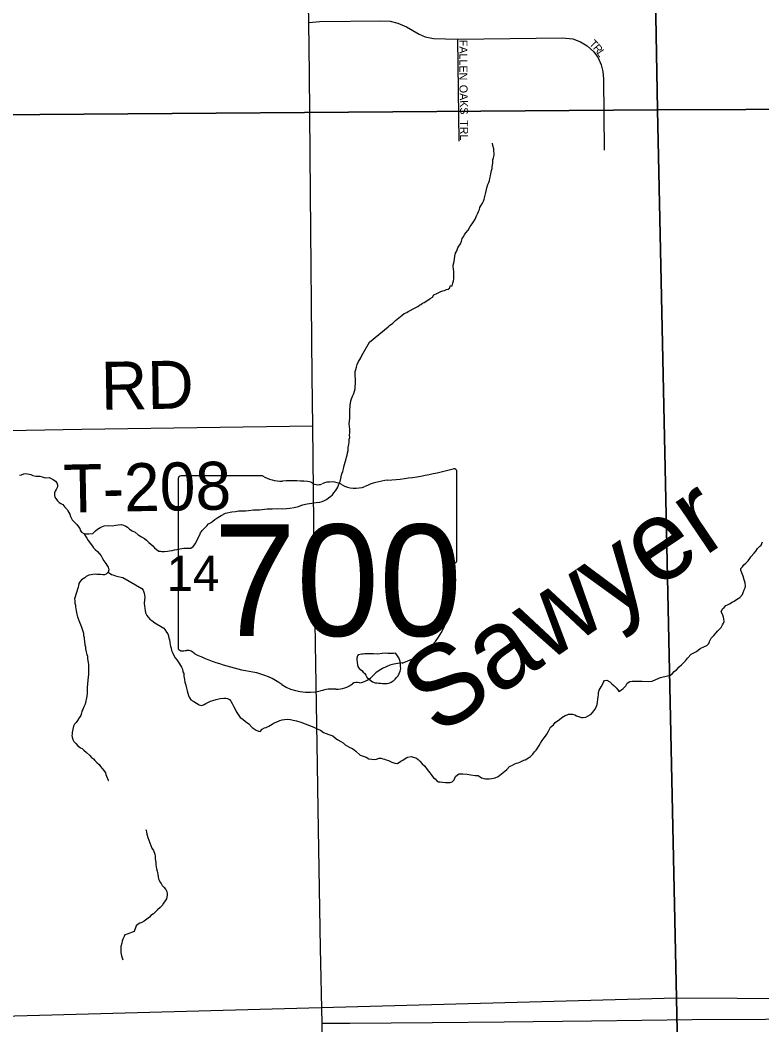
# Model space of a CAD drawing. Extents: x 10.6 to 44.6, y -2.6 to 23.4.
# Drawn here: x 17.431 to 18.308, y 16.595 to 17.784 of the extents above; entities that cross this region are included whole.
import ezdxf

# ---------------------------------------------------------------- set-up
doc = ezdxf.new("R2010")
doc.units = 0
for name, color, linetype in [('GM_X_Minor_Lake', 7, 'Continuous'), ('GM_X_Minor_River', 7, 'Continuous'), ('GM_X_Minor_River_Text', 7, 'Continuous'), ('GM_X_Section', 7, 'Continuous'), ('GM_X_Section_Text', 7, 'Continuous'), ('GM_X_State_Route', 7, 'Continuous'), ('GM_X_State_Shield', 7, 'Continuous'), ('GM_X_Township_Road', 7, 'Continuous'), ('GM_X_Township_Road_Text', 7, 'Continuous'), ('GM_X_Township_Subdivision', 7, 'Continuous'), ('GM_X_Township_Subdivision_Text', 7, 'Continuous')]:
    doc.layers.add(name, color=color, linetype=linetype)

msp = doc.modelspace()

# ---------------------------------------------------------------- linework, layer by layer
at = {"layer": 'GM_X_Minor_Lake'}
for points in [[(17.835, 17.0335), (17.8308, 17.0327), (17.8305, 17.0315), (17.8301, 17.0315), (17.829, 17.0288), (17.8291, 17.0269), (17.8295, 17.0235), (17.83, 17.0208), (17.8304, 17.019), (17.832, 17.0167), (17.8351, 17.0141), (17.8366, 17.0122), (17.8386, 17.0108), (17.8398, 17.0085), (17.841, 17.0063), (17.8441, 17.0037), (17.8479, 17.0007), (17.851, 16.9996), (17.8529, 16.9997), (17.8548, 16.9993), (17.8571, 16.999), (17.8594, 16.9987), (17.8617, 16.9987), (17.8651, 16.9988), (17.8681, 16.9996), (17.87, 17.0004), (17.8722, 17.0018)], [(17.8722, 17.0018), (17.8726, 17.002), (17.8745, 17.004), (17.876, 17.0059), (17.8782, 17.0079), (17.8793, 17.0105), (17.8804, 17.0132), (17.8811, 17.0167), (17.881, 17.019), (17.8809, 17.022), (17.8805, 17.025), (17.8797, 17.0273), (17.8789, 17.0292), (17.8765, 17.0326), (17.8749, 17.0348), (17.8727, 17.0344), (17.8677, 17.0343), (17.8658, 17.0342), (17.8631, 17.0345), (17.8593, 17.0341), (17.854, 17.0336), (17.8491, 17.0338), (17.843, 17.0337), (17.8388, 17.034), (17.8365, 17.0335), (17.835, 17.0335)]]:
    msp.add_lwpolyline(points, dxfattribs=at)
at = {"layer": 'GM_X_Minor_River'}
for points in [[(17.8442, 17.4026), (17.8661, 17.4207), (17.868, 17.4222), (17.8717, 17.4253), (17.8751, 17.4285), (17.8769, 17.43), (17.8788, 17.4316), (17.8807, 17.4331), (17.8829, 17.4347), (17.8852, 17.4367), (17.8882, 17.4379), (17.8901, 17.439), (17.8923, 17.4402), (17.8957, 17.4422), (17.8976, 17.443), (17.9013, 17.445), (17.9032, 17.4466), (17.9051, 17.4474), (17.907, 17.4489), (17.9088, 17.4497), (17.9122, 17.4517), (17.916, 17.4544), (17.9186, 17.456), (17.9204, 17.4587), (17.9238, 17.4603), (17.9284, 17.4627), (17.931, 17.4635), (17.9329, 17.4639), (17.9351, 17.4651), (17.9374, 17.4655), (17.9393, 17.4671), (17.9396, 17.4694), (17.9419, 17.4694), (17.9426, 17.4725), (17.9437, 17.4752), (17.944, 17.4778), (17.944, 17.4805), (17.9439, 17.4832), (17.9438, 17.4862), (17.9434, 17.4896), (17.9433, 17.4919), (17.9433, 17.4938), (17.9443, 17.498), (17.9447, 17.5007), (17.9453, 17.5045), (17.946, 17.5079), (17.9471, 17.5098), (17.9478, 17.5121), (17.9489, 17.5144), (17.95, 17.5164), (17.9519, 17.5191), (17.953, 17.5221), (17.954, 17.5252), (17.9551, 17.5271), (17.9566, 17.5298), (17.9581, 17.5321), (17.961, 17.5352), (17.9632, 17.5394), (17.9655, 17.5425), (17.9673, 17.5452), (17.9691, 17.5483), (17.9706, 17.5521), (17.9724, 17.5552), (17.9731, 17.5571), (17.9742, 17.5598), (17.9749, 17.5621), (17.976, 17.564), (17.9779, 17.5671), (17.979, 17.5694), (17.9797, 17.5717), (17.9818, 17.5797), (17.9825, 17.5832), (17.9832, 17.5851), (17.9842, 17.5893), (17.9853, 17.5916), (17.986, 17.5939), (17.9864, 17.5962), (17.9874, 17.5996), (17.9878, 17.6019), (17.9881, 17.6038), (17.9885, 17.6057), (17.9892, 17.608), (17.9895, 17.6099), (17.9898, 17.6126), (17.9902, 17.6145), (17.9901, 17.6183), (17.9908, 17.6206), (17.9915, 17.624), (17.9915, 17.6259), (17.9914, 17.629), (17.9913, 17.6313), (17.9901, 17.6354), (17.9897, 17.6381)], [(17.7648, 17.21), (17.7704, 17.2113), (17.7761, 17.2122), (17.7811, 17.213), (17.7856, 17.2135), (17.7883, 17.2143), (17.7909, 17.2155), (17.7935, 17.2167), (17.7958, 17.2183), (17.7984, 17.2203), (17.8006, 17.2222), (17.8021, 17.2242), (17.804, 17.2269), (17.8054, 17.2292), (17.8069, 17.2311), (17.808, 17.2346), (17.8094, 17.2377), (17.8115, 17.2468), (17.8126, 17.2495), (17.8133, 17.2526), (17.814, 17.2553), (17.8147, 17.2579), (17.8154, 17.2606), (17.8161, 17.2629), (17.8168, 17.2664), (17.8178, 17.269), (17.8182, 17.2717), (17.8189, 17.2744), (17.8191, 17.2782), (17.8198, 17.2816), (17.8201, 17.2847), (17.8201, 17.2877), (17.8208, 17.29), (17.8207, 17.2927), (17.821, 17.2958), (17.8209, 17.2996), (17.82, 17.306), (17.821, 17.3129), (17.8208, 17.3205), (17.8214, 17.3281), (17.8221, 17.3331), (17.8228, 17.3358), (17.8246, 17.3396), (17.8257, 17.3419), (17.8264, 17.3446), (17.8271, 17.3473), (17.8274, 17.3507), (17.8277, 17.3534), (17.8276, 17.3564), (17.8276, 17.3595), (17.8271, 17.3625), (17.8271, 17.3651), (17.8274, 17.3678), (17.8281, 17.3705), (17.8288, 17.3732), (17.8295, 17.3762), (17.8313, 17.3797), (17.8328, 17.382), (17.8338, 17.3843), (17.8353, 17.387), (17.8442, 17.4026)], [(17.4299, 17.2454), (17.4325, 17.2458), (17.4352, 17.2467), (17.4371, 17.2471), (17.4394, 17.2468), (17.4413, 17.2464), (17.4436, 17.2461), (17.4459, 17.245), (17.4493, 17.2443), (17.4512, 17.244), (17.4543, 17.2441), (17.4569, 17.2434), (17.4592, 17.2426), (17.4611, 17.2423), (17.465, 17.2424), (17.4676, 17.2413), (17.47, 17.2402), (17.4727, 17.238), (17.4742, 17.2361)], [(17.4742, 17.2361), (17.475, 17.2339), (17.4751, 17.2316), (17.4733, 17.2285), (17.4722, 17.2262), (17.4715, 17.2243), (17.4715, 17.2212), (17.4719, 17.2193), (17.4731, 17.2175), (17.4751, 17.2148), (17.477, 17.213), (17.479, 17.2119), (17.4813, 17.2104), (17.4836, 17.2074), (17.4864, 17.2048), (17.4872, 17.2029), (17.4883, 17.2011), (17.4895, 17.1992), (17.4904, 17.1965), (17.4924, 17.1924), (17.4955, 17.1894), (17.4978, 17.1868), (17.4998, 17.1842), (17.5013, 17.182), (17.5018, 17.1801), (17.5033, 17.1778), (17.506, 17.1764), (17.5091, 17.176), (17.5121, 17.1757), (17.5167, 17.1762), (17.52, 17.1793), (17.5223, 17.1813), (17.5245, 17.1825), (17.5264, 17.1837), (17.5302, 17.1853), (17.5355, 17.1858), (17.5397, 17.1855), (17.5439, 17.186), (17.5469, 17.1864), (17.5503, 17.1869), (17.553, 17.1862), (17.5557, 17.1851), (17.558, 17.1836), (17.5603, 17.1814), (17.5634, 17.1796), (17.5669, 17.1777), (17.5704, 17.1748), (17.5746, 17.1722), (17.5781, 17.1704), (17.5804, 17.1682), (17.5831, 17.1655), (17.5855, 17.1637), (17.5878, 17.1615), (17.5898, 17.1592), (17.5921, 17.1574), (17.5948, 17.1555), (17.5967, 17.1552), (17.5986, 17.1549), (17.6016, 17.1549), (17.6051, 17.1554), (17.6077, 17.1558), (17.6108, 17.1563), (17.6134, 17.1571), (17.6164, 17.1572), (17.6198, 17.158), (17.6244, 17.1589), (17.6286, 17.159), (17.6328, 17.1591), (17.6354, 17.161), (17.6383, 17.1645), (17.6416, 17.1711), (17.6434, 17.1745), (17.6441, 17.1772), (17.6467, 17.1803), (17.649, 17.1826), (17.6516, 17.1854), (17.6538, 17.1877), (17.6568, 17.1893), (17.659, 17.1909), (17.6613, 17.1928), (17.6647, 17.1952), (17.6688, 17.1976), (17.6737, 17.2003), (17.6812, 17.202), (17.6858, 17.2025), (17.6896, 17.203), (17.6926, 17.203), (17.6949, 17.2031), (17.6976, 17.2032), (17.701, 17.2036), (17.7071, 17.2041), (17.7139, 17.2043), (17.723, 17.2053), (17.7291, 17.2054), (17.7359, 17.2059), (17.7413, 17.2053), (17.7458, 17.2058), (17.75, 17.2062), (17.7549, 17.2071), (17.7602, 17.2084), (17.7648, 17.21)], [(17.506, 17.1764), (17.5096, 17.1707), (17.5112, 17.1681), (17.5163, 17.1614), (17.5175, 17.1595), (17.5194, 17.1573), (17.5225, 17.155), (17.5248, 17.1524), (17.5268, 17.1498), (17.5284, 17.1468), (17.53, 17.1438), (17.5323, 17.1408), (17.5335, 17.1389), (17.5351, 17.1363), (17.5356, 17.1333), (17.5349, 17.1306), (17.5326, 17.1283), (17.5307, 17.1275), (17.5285, 17.1274), (17.5258, 17.1277), (17.5235, 17.1277), (17.5216, 17.1276), (17.5197, 17.128), (17.5167, 17.1279), (17.5148, 17.1275), (17.5121, 17.127), (17.5091, 17.1254), (17.5072, 17.1239), (17.5054, 17.1227), (17.5035, 17.1215), (17.5013, 17.1192), (17.5002, 17.1172), (17.4998, 17.1142), (17.4994, 17.1126)], [(18.2849, 17.1297), (18.2836, 17.1327), (18.2836, 17.135), (18.2854, 17.137), (18.2873, 17.1393), (18.2895, 17.1412), (18.2921, 17.144), (18.2944, 17.1467), (18.2955, 17.1486), (18.2995, 17.1529), (18.3014, 17.1552), (18.3032, 17.1587), (18.3058, 17.161), (18.3077, 17.1626), (18.3091, 17.1664)], [(17.5349, 17.1306), (17.5391, 17.1276), (17.5418, 17.1269), (17.5437, 17.1262), (17.5468, 17.1255), (17.5502, 17.1248), (17.5525, 17.1244)], [(17.5525, 17.1244), (17.5749, 17.1113), (17.5764, 17.1091), (17.5777, 17.1057), (17.5781, 17.1038), (17.5782, 17.1007), (17.5778, 17.0977), (17.5776, 17.0935), (17.578, 17.0905), (17.5785, 17.0874), (17.5789, 17.0852), (17.5793, 17.0825), (17.5809, 17.0791), (17.5821, 17.0772), (17.5841, 17.075), (17.5868, 17.0732), (17.5903, 17.0706), (17.5987, 17.0654), (17.6007, 17.0643), (17.6022, 17.0625), (17.6038, 17.0595), (17.6054, 17.0576), (17.6062, 17.055), (17.6067, 17.0523), (17.6075, 17.0504), (17.6079, 17.0478), (17.6084, 17.0447), (17.6088, 17.0428), (17.6096, 17.0406), (17.61, 17.0379), (17.6109, 17.0353), (17.6125, 17.0319), (17.6144, 17.0293), (17.6164, 17.0267), (17.6195, 17.0222), (17.6219, 17.018), (17.6231, 17.0158), (17.6235, 17.0127), (17.6244, 17.0105), (17.6244, 17.0074), (17.6253, 17.0036), (17.6257, 17.0002), (17.627, 16.9968), (17.6278, 16.9934), (17.6286, 16.99), (17.6291, 16.9874), (17.6299, 16.9847), (17.6307, 16.9828), (17.6327, 16.9795), (17.6365, 16.9773), (17.6396, 16.9754), (17.6427, 16.9736), (17.6458, 16.9729), (17.6484, 16.9741), (17.6507, 16.9753), (17.6529, 16.9765), (17.6559, 16.9777), (17.659, 16.9785), (17.6627, 16.9798), (17.6673, 16.981), (17.6718, 16.9815), (17.6741, 16.9815), (17.676, 16.9812), (17.6787, 16.9797), (17.6803, 16.9779), (17.6815, 16.9752), (17.6831, 16.9718), (17.685, 16.9692), (17.6862, 16.9666), (17.6871, 16.9643), (17.6886, 16.9621), (17.691, 16.9587), (17.6945, 16.9565), (17.6976, 16.9539), (17.7014, 16.951), (17.7053, 16.9469), (17.71, 16.9435), (17.713, 16.9425), (17.715, 16.9421), (17.7172, 16.9448), (17.7198, 16.9464), (17.7221, 16.9469), (17.7251, 16.9484), (17.727, 16.9493), (17.7292, 16.9508), (17.7315, 16.9524), (17.7337, 16.9532), (17.7379, 16.9552), (17.7409, 16.9557), (17.7436, 16.9561)], [(18.0618, 16.95), (18.064, 16.9527), (18.0666, 16.9547), (18.0685, 16.9559), (18.0719, 16.9586), (18.0737, 16.9598), (18.0756, 16.961), (18.0779, 16.9618), (18.0798, 16.9626), (18.0824, 16.9626), (18.0843, 16.9627), (18.087, 16.9616), (18.0893, 16.9605), (18.0913, 16.9598), (18.0951, 16.9587), (18.097, 16.9584), (18.1, 16.9589), (18.1064, 16.9624), (18.1086, 16.9648), (18.1108, 16.9682), (18.113, 16.9725), (18.1141, 16.9763), (18.1144, 16.9801), (18.1147, 16.9832), (18.115, 16.9855), (18.115, 16.9881), (18.116, 16.9908), (18.1182, 16.995), (18.1197, 16.9977), (18.1211, 17.0004), (18.1222, 17.0024), (18.1249, 17.0028), (18.1287, 17.0006), (18.1311, 16.9984), (18.1338, 16.9962), (18.1361, 16.9935), (18.1381, 16.9913), (18.1393, 16.9894), (18.1423, 16.9914), (18.1445, 16.993), (18.1475, 16.9961), (18.1489, 16.9992), (18.1523, 17.0011), (18.155, 17.0016), (18.1573, 17.0016), (18.1592, 17.0017), (18.1618, 17.0014), (18.1645, 17.0014), (18.1668, 17.0015), (18.1744, 17.0013), (18.1786, 17.0014), (18.1831, 17.0037), (18.1884, 17.0058), (18.1967, 17.0079), (18.2005, 17.0087), (18.2023, 17.0103), (18.2046, 17.013), (18.2079, 17.0153), (18.2105, 17.0184), (18.2135, 17.0208), (18.2158, 17.0231), (18.218, 17.0255), (18.2206, 17.0286), (18.2246, 17.0336), (18.231, 17.0368), (18.2355, 17.0403), (18.2404, 17.0427), (18.2434, 17.0439), (18.2457, 17.0463), (18.2464, 17.0486), (18.2486, 17.0524), (18.2515, 17.0555), (18.2541, 17.0582), (18.2564, 17.061), (18.2601, 17.0652), (18.2619, 17.0683), (18.263, 17.0702), (18.2637, 17.0722), (18.2636, 17.0752), (18.2632, 17.0771), (18.262, 17.0809), (18.2604, 17.0835), (18.2619, 17.087), (18.2637, 17.0889), (18.266, 17.0909), (18.2678, 17.0917), (18.2701, 17.0932), (18.2735, 17.0952), (18.2757, 17.0964), (18.2783, 17.098), (18.2806, 17.0992), (18.2825, 17.1007), (18.2854, 17.1042), (18.2865, 17.1065), (18.2876, 17.1096), (18.2887, 17.1119), (18.289, 17.1138), (18.2885, 17.118), (18.2877, 17.1214), (18.2865, 17.1256), (18.2849, 17.1297)], [(17.4994, 17.1126), (17.4952, 17.0989), (17.4957, 17.0966), (17.4957, 17.0939), (17.4962, 17.0913), (17.4962, 17.0894), (17.4967, 17.0871), (17.4971, 17.0848), (17.4979, 17.081), (17.4988, 17.0776), (17.5, 17.0746), (17.5012, 17.0712), (17.5024, 17.0686), (17.5036, 17.0656), (17.5057, 17.0584), (17.5057, 17.0557), (17.5066, 17.0531), (17.5066, 17.0508), (17.507, 17.0489), (17.5075, 17.0444), (17.508, 17.0421), (17.508, 17.0398), (17.5089, 17.0364), (17.5097, 17.033), (17.5105, 17.0311), (17.5106, 17.0284), (17.511, 17.0258), (17.5114, 17.0235), (17.5115, 17.0212), (17.5116, 17.0178), (17.5117, 17.0136), (17.5117, 17.0098), (17.5114, 17.0064), (17.5111, 17.0026), (17.5105, 16.9984), (17.5102, 16.9942), (17.5103, 16.9911), (17.51, 16.9873), (17.5097, 16.9839), (17.5076, 16.9743), (17.5062, 16.9713), (17.5051, 16.9682), (17.504, 16.9659), (17.5033, 16.9636), (17.5026, 16.9609), (17.5007, 16.9582), (17.4985, 16.9551), (17.4971, 16.9528), (17.4952, 16.9505), (17.4941, 16.9485), (17.4931, 16.9447), (17.4927, 16.9428), (17.4924, 16.9409), (17.4924, 16.939), (17.4921, 16.9371), (17.4925, 16.9352), (17.4933, 16.9325), (17.4945, 16.9303), (17.4969, 16.9277), (17.4992, 16.9251), (17.5023, 16.9228), (17.5042, 16.9218), (17.5062, 16.9199), (17.5093, 16.9173), (17.5128, 16.914), (17.5151, 16.9113), (17.5175, 16.9095), (17.519, 16.9076), (17.5217, 16.9054), (17.5245, 16.9028), (17.526, 16.9006), (17.528, 16.8983), (17.53, 16.8957), (17.5319, 16.8931), (17.5323, 16.8912), (17.5331, 16.8893), (17.5348, 16.8844), (17.5348, 16.884), (17.5352, 16.884)], [(17.7436, 16.9561), (17.7474, 16.9566), (17.7508, 16.9563), (17.7538, 16.9556), (17.758, 16.9545), (17.763, 16.9531), (17.7784, 16.947), (17.7822, 16.9452), (17.7861, 16.9434), (17.7899, 16.9408), (17.7961, 16.9386), (17.8007, 16.9368), (17.8038, 16.9343), (17.8069, 16.932), (17.8104, 16.9302), (17.8131, 16.9284), (17.8154, 16.9261), (17.8181, 16.9247), (17.8208, 16.9232), (17.8242, 16.9218), (17.8281, 16.9188), (17.8332, 16.914), (17.8401, 16.9115), (17.8435, 16.9097), (17.847, 16.9094), (17.85, 16.909), (17.8523, 16.9091), (17.8557, 16.9103), (17.858, 16.9104), (17.8599, 16.9096), (17.8618, 16.9093), (17.8641, 16.9086), (17.8668, 16.9075), (17.8707, 16.9057), (17.8741, 16.9046), (17.8772, 16.9043), (17.8813, 16.9067), (17.8835, 16.9079), (17.8854, 16.9091), (17.8892, 16.9115), (17.8933, 16.9123), (17.8998, 16.9106), (17.9018, 16.9087), (17.9037, 16.9068), (17.9065, 16.9039), (17.9096, 16.9009), (17.9123, 16.8971), (17.9155, 16.893), (17.9178, 16.89), (17.9198, 16.887), (17.9217, 16.8859), (17.9237, 16.8837), (17.926, 16.8826), (17.9279, 16.8823), (17.9306, 16.882), (17.934, 16.8816), (17.9374, 16.8817), (17.9397, 16.8818), (17.942, 16.8826), (17.9442, 16.8849), (17.946, 16.8888), (17.9482, 16.8907), (17.9501, 16.8919), (17.9547, 16.892), (17.9596, 16.8914), (17.9642, 16.8907), (17.9692, 16.8901), (17.9726, 16.8898), (17.9769, 16.8872), (17.9795, 16.8865), (17.9814, 16.8861), (17.9856, 16.8859), (17.9891, 16.8863), (17.9928, 16.8872), (17.9966, 16.8888), (18.0045, 16.895), (18.0067, 16.897), (18.01, 16.9005), (18.0134, 16.9021), (18.0161, 16.9037), (18.0183, 16.9045), (18.0202, 16.9049), (18.0221, 16.9057), (18.0243, 16.9069), (18.0266, 16.9081), (18.0285, 16.9085), (18.0322, 16.9109), (18.0345, 16.9125), (18.0375, 16.9152), (18.0393, 16.9179), (18.0412, 16.9198), (18.043, 16.9222), (18.0449, 16.9253), (18.0467, 16.9283), (18.0485, 16.9314), (18.0507, 16.9345), (18.0526, 16.9365), (18.0541, 16.9388), (18.0559, 16.9423), (18.0584, 16.9473), (18.0618, 16.95)], [(17.5795, 16.826), (17.5799, 16.8249), (17.5803, 16.8234), (17.5808, 16.8204), (17.582, 16.8166), (17.5868, 16.8041), (17.5888, 16.8011), (17.59, 16.797), (17.5905, 16.7943), (17.5906, 16.7913), (17.591, 16.7894), (17.5914, 16.7867), (17.5915, 16.7841), (17.5919, 16.7818), (17.5923, 16.7795), (17.5928, 16.7769), (17.5932, 16.775), (17.5936, 16.7727), (17.5941, 16.7701), (17.5945, 16.7678), (17.5953, 16.7659), (17.5961, 16.764), (17.5977, 16.7621), (17.5989, 16.7599), (17.6008, 16.7577), (17.6032, 16.755), (17.6044, 16.7528), (17.6048, 16.7505), (17.6048, 16.7486), (17.6045, 16.7459), (17.6038, 16.744), (17.6023, 16.7417), (17.6005, 16.739), (17.5987, 16.7363), (17.5964, 16.7336), (17.5935, 16.7309), (17.5908, 16.7285), (17.5886, 16.7262), (17.5856, 16.7242), (17.5838, 16.7223), (17.5808, 16.7199), (17.5774, 16.7175), (17.5748, 16.716), (17.5725, 16.7152), (17.5706, 16.714), (17.568, 16.712), (17.5659, 16.7055), (17.5576, 16.7023), (17.5546, 16.7014), (17.5538, 16.6995), (17.5524, 16.6964), (17.5517, 16.6938), (17.551, 16.6915), (17.5499, 16.6876), (17.55, 16.6842), (17.55, 16.6823), (17.5501, 16.6804), (17.5509, 16.6766), (17.5514, 16.674), (17.5522, 16.6717)]]:
    msp.add_lwpolyline(points, dxfattribs=at)
at = {"layer": 'GM_X_Section'}
for points in [[(17.2198, 18.8008), (18.1646, 18.8031), (18.1656, 18.7612), (18.1848, 17.6775), (17.2448, 17.6704)], [(18.1656, 18.7612), (19.1006, 18.7791), (19.125, 17.681), (18.1848, 17.6775)], [(18.1848, 17.6775), (19.125, 17.681), (19.1418, 16.6213), (18.2074, 16.6265)], [(17.2448, 17.6704), (18.1848, 17.6775), (18.2074, 16.6265), (17.2647, 16.6007)]]:
    msp.add_lwpolyline(points, close=True, dxfattribs=at)
for points in [[(18.2299, 15.5267), (18.2074, 16.6265), (17.2647, 16.6007), (17.2881, 15.5267)], [(19.1603, 15.5267), (19.1419, 16.6116), (19.1419, 16.6144), (19.1418, 16.6213), (18.2074, 16.6265), (18.2299, 15.5267)]]:
    msp.add_lwpolyline(points, dxfattribs=at)
at = {"layer": 'GM_X_State_Route'}
msp.add_lwpolyline([(17.8012, 15.5267), (17.7999, 15.6245), (17.7994, 15.6969), (17.798, 15.8329), (17.7956, 16.0407), (17.7937, 16.2499), (17.7904, 16.4688), (17.788, 16.5964), (17.7861, 16.6856), (17.7836, 16.85), (17.7826, 16.9026), (17.7801, 17.0459), (17.7792, 17.124), (17.7789, 17.1502), (17.7773, 17.3034), (17.7765, 17.3624), (17.7744, 17.5784), (17.7731, 17.7202), (17.7723, 17.7811), (17.7695, 17.9272), (17.7683, 17.9968), (17.7654, 18.1426), (17.7636, 18.2173)], dxfattribs=at)
at = {"layer": 'GM_X_State_Shield'}
for p, q in [((17.6179, 17.2412), (17.6179, 17.041)), ((17.7177, 17.2446), (17.6212, 17.2446)), ((17.9475, 17.1449), (17.9475, 17.2496)), ((17.9475, 17.1449), (17.9475, 17.1449))]:
    msp.add_line(p, q, dxfattribs=at)
for centre, major_axis, start_param, end_param in [((17.8301, 17.5174), (0.3495, 0), 4.814394, 5.042369), ((17.9439, 17.25), (0.00367, 0), 6.141152, 7.989035), ((17.6217, 17.2416), (0.00382, 0), 1.712693, 3.28349), ((17.7407, 17.2678), (0.037, 0), 4.042523, 4.731795), ((17.753, 17.1322), (0.133, 0), 1.404758, 1.657858), ((17.7831, 17.2426), (0.0107, 0), 3.836095, 5.185415), ((17.7988, 17.2195), (0.0222, 0), 0.950623, 2.079405), ((17.8275, 17.2512), (0.0267, 0), 4.081561, 5.145723), ((17.8747, 17.1835), (0.0703, 0), 1.699011, 2.107814), ((17.9436, 17.1445), (0.00393, 0), 5.05454, 6.418171), ((17.9467, 17.1372), (0.00568, 0), 1.883978, 3.671073), ((17.9105, 17.124), (0.0341, 0), 5.934695, 6.695948), ((17.9607, 17.1011), (0.0248, 0), 2.387724, 3.262537), ((17.8497, 17.0877), (0.0874, 0), 5.101752, 6.440018), ((17.6217, 17.0406), (0.00385, 0), 3.00124, 4.508301), ((17.6223, 17.0611), (0.0294, 0), 4.665946, 4.897461), ((17.6283, 17.0295), (0.0106, 0), 0.519207, 1.627899), ((17.7622, 17.2093), (0.2524, 0), 4.195997, 4.488961), ((17.8866, 16.9849), (0.0479, 0), 1.647645, 2.488434), ((17.6869, 16.9511), (0.079, 0), 0.823519, 1.323587), ((17.8259, 17.0216), (0.0282, 0), 4.937069, 5.64225), ((17.7723, 17.0285), (0.0501, 0), 4.026481, 4.996735), ((17.8013, 16.9593), (0.0412, 0), 1.495662, 1.94098), ((17.8049, 17.0135), (0.0267, 0), 4.691044, 5.507374), ((17.8291, 16.9941), (0.00752, 0), 1.147584, 2.315152)]:
    msp.add_ellipse(centre, major_axis=major_axis, ratio=0.8, start_param=start_param, end_param=end_param, dxfattribs=at)
at = {"layer": 'GM_X_Township_Road'}
for points in [[(17.7773, 17.3034), (17.64, 17.3013), (17.5039, 17.2992), (17.3496, 17.2964), (17.2745, 17.2952), (17.2723, 17.2948)], [(19.5991, 16.6126), (19.5366, 16.6119), (19.2619, 16.6095), (18.9861, 16.6077), (18.7284, 16.6054), (18.6038, 16.6042), (18.5905, 16.6049), (18.4954, 16.6035), (18.4056, 16.6021), (18.3128, 16.6014), (18.2258, 16.6007), (18.107, 16.5993), (18.0035, 16.5982), (17.9186, 16.5972), (17.821, 16.5964), (17.788, 16.5964)]]:
    msp.add_lwpolyline(points, dxfattribs=at)
at = {"layer": 'GM_X_Township_Subdivision'}
for points in [[(17.7723, 17.7811), (17.7855, 17.7819), (17.8575, 17.783), (17.8686, 17.7824), (17.8779, 17.7803), (17.888, 17.7756), (17.9028, 17.7671), (17.9102, 17.7639), (17.92, 17.7621), (17.9483, 17.7613), (18.0724, 17.7626), (18.0846, 17.7615), (18.0939, 17.7581), (18.1018, 17.7531), (18.1095, 17.7462), (18.1148, 17.739), (18.1182, 17.7308), (18.1201, 17.7231), (18.1209, 17.7144), (18.1219, 17.6297)], [(17.9483, 17.7613), (17.9499, 17.6403)]]:
    msp.add_lwpolyline(points, dxfattribs=at)

# ---------------------------------------------------------------- texts
at = {"layer": 'GM_X_Minor_River_Text'}
msp.add_text('Sawyer', height=0.09476, rotation=34.0166, dxfattribs=at).set_placement((17.9248, 16.9356))
at = {"layer": 'GM_X_Section_Text'}
msp.add_text('14', height=0.04186, rotation=0, dxfattribs=at).set_placement((17.6042, 17.1083))
at = {"layer": 'GM_X_State_Shield'}
msp.add_text('700', height=0.13184, dxfattribs=at).set_placement((17.6595, 17.0551))
at = {"layer": 'GM_X_Township_Road_Text'}
for s, rotation, p in [('RD', 0.9872, (17.5268, 17.3225)), ('T-208', 1.1178, (17.4825, 17.2009))]:
    msp.add_text(s, height=0.05682, rotation=rotation, dxfattribs=at).set_placement(p)
at = {"layer": 'GM_X_Township_Subdivision_Text'}
for s, rotation, p in [('FALLEN', 270, (17.9506, 17.7604)), ('T', 314.6909, (18.1034, 17.755)), ('R', 310.1009, (18.108, 17.7504)), ('L', 304.175, (18.1126, 17.7449)), ('OAKS', 271.5067, (17.9506, 17.7071)), ('TRL', 270, (17.9514, 17.6654))]:
    msp.add_text(s, height=0.00947, rotation=rotation, dxfattribs=at).set_placement(p)

doc.saveas('drawing.dxf')
